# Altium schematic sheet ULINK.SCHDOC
size A4
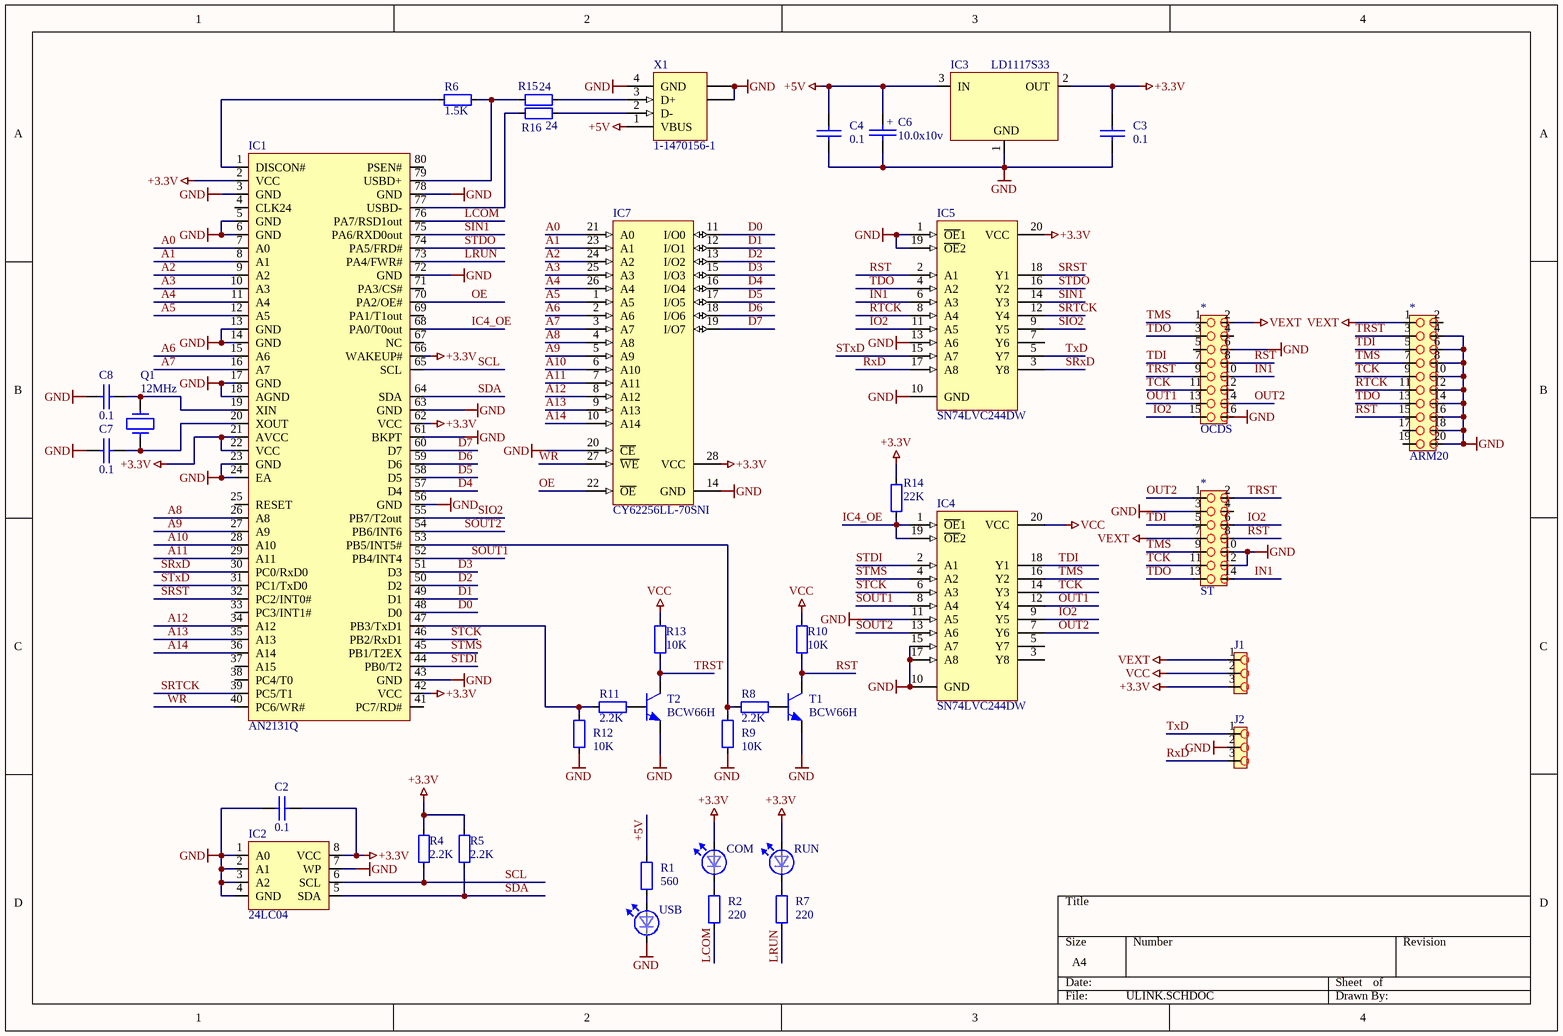
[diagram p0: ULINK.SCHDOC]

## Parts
(Parts that share a designator on the sheet are numbered #1, #2 ... from top to bottom, then left to right.)
*#1  OCDS  [HDR2X8]
*#2  ARM20  [HDR2X10]
*#3  ST  [MHDR2X7]
C2  0.1  [CC2013-0805]
C3  0.1  [CC2013-0805]
C4  0.1  [CC2013-0805]
C6  10.0x10v  [Tant.Cap. 3.5*2.8]
C7  0.1  [CC2013-0805]
C8  0.1  [CC2013-0805]
COM  SMD_LED  [DL-35]  (value not drawn)
IC1  AN2131Q  [Quad80]
IC2  24LC04  [SO-8]
IC3  LD1117S33  [SOT-223]
IC4  SN74LVC244DW  [DW020]
IC5  SN74LVC244DW  [DW020]
IC7  CY62256LL-70SNI  [S22]
J1  3pin_jumper  [HDR1X3]  (value not drawn)
J2  3pin_jumper  [HDR1X3]  (value not drawn)
Q1  12MHz  [HC-49U]
R1  560  [2012[0805]]
R2  220  [2012[0805]]
R4  2.2K  [2012[0805]]
R5  2.2K  [2012[0805]]
R6  1.5K  [2012[0805]]
R7  220  [2012[0805]]
R8  2.2K  [2012[0805]]
R9  10K  [2012[0805]]
R10  10K  [2012[0805]]
R11  2.2K  [2012[0805]]
R12  10K  [2012[0805]]
R13  10K  [2012[0805]]
R14  22K  [2012[0805]]
R15  24  [2012[0805]]
R16  24  [2012[0805]]
RUN  SMD_LED  [DL-35]  (value not drawn)
T1  BCW66H  [SOT23]
T2  BCW66H  [SOT23]
USB  SMD_LED  [DL-35]  (value not drawn)
X1  1-1470156-1  [USB 1470156]

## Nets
+3.3V: C2.2 C3.1 COM.2(A) IC1.2(VCC) IC1.21(AVCC) IC1.22(VCC) IC1.42(VCC) IC1.62(VCC) IC1.66(WAKEUP#) IC2.8(VCC) IC3.2(OUT) IC5.20(VCC) IC7.28(VCC) J1.3 R4.2 R5.2 R14.1 RUN.2(A)
+5V: C4.1 C6.1 IC3.3(IN) R1.2 X1.1(VBUS)
GND: *#1.6 *#1.16 *#2.4 *#2.6 *#2.8 *#2.10 *#2.12 *#2.14 *#2.16 *#2.18 *#2.20 *#3.3 *#3.10 *#3.12 C2.1 C3.2 C4.2 C6.2 C7.1 C8.1 IC1.3(GND) IC1.5(GND) IC1.6(GND) IC1.13(GND) IC1.14(GND) IC1.17(GND) IC1.18(AGND) IC1.23(GND) IC1.24(EA) IC1.43(GND) IC1.56(GND) IC1.61(BKPT) IC1.63(GND) IC1.72(GND) IC1.78(GND) IC2.1(A0) IC2.2(A1) IC2.3(A2) IC2.4(GND) IC2.7(WP) IC3.1(GND) IC4.10(GND) IC4.11(A5) IC4.15(A7) IC4.17(A8) IC5.1(~{OE}1) IC5.10(GND) IC5.13(A6) IC5.19(~{OE}2) IC7.14(GND) IC7.20(~{CE}) J2.2 R9.1 R12.1 T1.2(E) T2.2(E) USB.1(C) X1.4(GND) X1.5(SHLD) X1.6(SHLD)
VCC: IC4.20(VCC) J1.2 R10.2 R13.2
VEXT: *#1.2 *#2.1 *#3.7 J1.1
A0: IC1.7(A0) IC7.21(A0)
A1: IC1.8(A1) IC7.23(A1)
A2: IC1.9(A2) IC7.24(A2)
A3: IC1.10(A3) IC7.25(A3)
A4: IC1.11(A4) IC7.26(A4)
A5: IC1.12(A5) IC7.1(A5)
A6: IC1.15(A6) IC7.2(A6)
A7: IC1.16(A7) IC7.3(A7)
A8: IC1.26(A8) IC7.4(A8)
A9: IC1.27(A9) IC7.5(A9)
A10: IC1.28(A10) IC7.6(A10)
A11: IC1.29(A11) IC7.7(A11)
A12: IC1.34(A12) IC7.8(A12)
A13: IC1.35(A13) IC7.9(A13)
A14: IC1.36(A14) IC7.10(A14)
D0: IC1.48(D0) IC7.11(I/O0)
D1: IC1.49(D1) IC7.12(I/O1)
D2: IC1.50(D2) IC7.13(I/O2)
D3: IC1.51(D3) IC7.15(I/O3)
D4: IC1.57(D4) IC7.16(I/O4)
D5: IC1.58(D5) IC7.17(I/O5)
D6: IC1.59(D6) IC7.18(I/O6)
D7: IC1.60(D7) IC7.19(I/O7)
IC4_OE: IC1.68(PA0/T0out) IC4.1(~{OE}1) IC4.19(~{OE}2) R14.2
IN1: *#1.10 *#3.14 IC5.6(A3)
IO2: *#1.15 *#3.6 IC4.9(Y5) IC5.11(A5)
LCOM: IC1.76(PA7/RSD1out) R2.1
LRUN: IC1.73(PA4/FWR#) R7.1
OE: IC1.70(PA2/OE#) IC7.22(~{OE})
OUT1: *#1.13 IC4.12(Y4)
OUT2: *#1.14 *#3.1 IC4.7(Y6)
RST: *#1.8 *#2.15 *#3.8 IC5.2(A1) R10.1 T1.3(C)
RTCK: *#2.11 IC5.8(A4)
RxD: IC5.17(A8) J2.3
SCL: IC1.65(SCL) IC2.6(SCL) R4.1
SDA: IC1.64(SDA) IC2.5(SDA) R5.1
SIN1: IC1.75(PA6/RXD0out) IC5.14(Y3)
SIO2: IC1.55(PB7/T2out) IC5.9(Y5)
SOUT1: IC1.52(PB4/INT4) IC4.8(A4)
SOUT2: IC1.54(PB6/INT6) IC4.13(A6)
SRST: IC1.32(PC2/INT0#) IC5.18(Y1)
SRTCK: IC1.39(PC5/T1) IC5.12(Y4)
SRxD: IC1.30(PC0/RxD0) IC5.3(Y8)
STCK: IC1.46(PB2/RxD1) IC4.6(A3)
STDI: IC1.44(PB0/T2) IC4.2(A1)
STDO: IC1.74(PA5/FRD#) IC5.16(Y2)
STMS: IC1.45(PB1/T2EX) IC4.4(A2)
STxD: IC1.31(PC1/TxD0) IC5.15(A7)
TCK: *#1.11 *#2.9 *#3.11 IC4.14(Y3)
TDI: *#1.7 *#2.5 *#3.5 IC4.18(Y1)
TDO: *#1.3 *#2.13 *#3.13 IC5.4(A2)
TMS: *#1.1 *#2.7 *#3.9 IC4.16(Y2)
TRST: *#1.9 *#2.3 *#3.2 R13.1 T2.3(C)
TxD: IC5.5(Y7) J2.1
WR: IC1.40(PC6/WR#) IC7.27(~{WE})
NetC7_2: C7.2 IC1.20(XOUT) Q1.2
NetC8_2: C8.2 IC1.19(XIN) Q1.1
NetCOM_1: COM.1(C) R2.2
NetIC1_1: IC1.1(DISCON#) R6.2
NetIC1_47: IC1.47(PB3/TxD1) R11.2 R12.2
NetIC1_53: IC1.53(PB5/INT5#) R8.2 R9.2
NetIC1_77: IC1.77(USBD-) R16.1
NetIC1_79: IC1.79(USBD+) R6.1 R15.1
NetR1_1: R1.1 USB.2(A)
NetR7_2: R7.2 RUN.1(C)
NetR8_1: R8.1 T1.1(B)
NetR11_1: R11.1 T2.1(B)
NetR15_2: R15.2 X1.3(D+)
NetR16_2: R16.2 X1.2(D-)

Not connected (* = marked no-connect by the designer): *#1 4 5 12; *#2 2 17 19; *#3 4; IC1 4(CLK24) 25(RESET) 33(PC3/INT1#) 37(A15) 38(PC4/T0) 41(PC7/RD#) 67(NC) 69(PA1/T1out) 71(PA3/CS#) 80(PSEN#); IC4 3(Y8) 5(Y7); IC5 7(Y6)

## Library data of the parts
*#1 = ST
*#3 = OCDS
C2-C4 C7 C8 = C0805: Chip Capacitor 0805; Description in catalog: SMD-Resistor 0805 0R; ID in cataloge: 0
C6 = CTUF010CFT: Tantalum capacitor, SMD, type B, 10.0 uF 10V; Description in catalog: SMD-Resistor 0805 0R; ID in cataloge: 0
IC3 = LD1117S33: Low drop positive voltage regulator, 3.3 V, 1A, SOT-223
IC4 IC5 = SN74LVC244DW: Octal Buffer/Driver with 3-State Outputs; ComponentAvailability: Obsolete
IC7 = CY62256LL-70SNI: 32K x 8 Static RAM
Q1 = XT49S1105: Vishay/Dale XT49M Microprocessor Crystals 12MHZ
R1 R2 R4-R16 = R0805: Resistor 0805; Description in catalog: SMD-Resistor 0805 1/8W 1% 10K; ID in cataloge: CR0805K010-1; Min. order qty: 1000
T1 T2 = BCW66H: NPN transistor VCEsat=0.7 V max Ic=500 mA, Ib=50 mA; Description in catalog: SMD-Resistor 0805 0R; ID in cataloge: 0
X1 = 1-1470156-1: USB 1.1, Right Angle, Thru-Hole, B Type, Receptacle, 4 Position, White; ContactMaterial: Phosphor Bronze; ContactPlating: Gold over Nickel; TerminationLength: 3.00mm [0.118in.]; PCB_Layout: Complies with manufacturer's recommendation.; DrillSize: Corresponds to nominal value.; PanelGround: Without; Description in catalog: SMD-Resistor 0805 0R; ID in cataloge: 0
